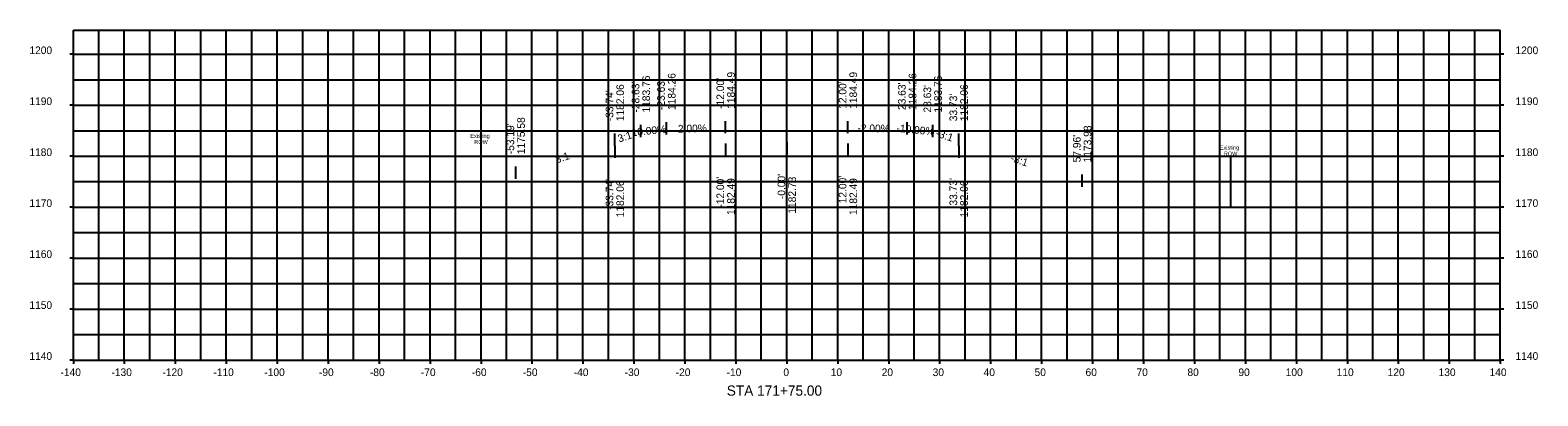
# Model space of a CAD drawing. Extents: x -148 to 147, y 1133 to 1205.
import ezdxf

# ---------------------------------------------------------------- set-up
doc = ezdxf.new("R2010")
doc.units = 0
for name, color, linetype in [('SheetBorder', 7, 'Continuous'), ('SheetGridMajor', 7, 'Continuous'), ('SheetGridMinor', 7, 'Continuous'), ('SheetText', 7, 'Continuous'), ('TC_Grading', 7, 'Continuous'), ('Text', 7, 'Continuous')]:
    doc.layers.add(name, color=color, linetype=linetype)

msp = doc.modelspace()

# ---------------------------------------------------------------- linework, layer by layer
at = {"layer": 'SheetBorder'}
for p, q in [((-140, 1204.73), (140, 1204.73)), ((-140, 1140), (-140, 1204.73)), ((140, 1140), (140, 1204.73)), ((-140, 1140), (140, 1140))]:
    msp.add_line(p, q, dxfattribs=at)
at = {"layer": 'SheetGridMajor'}
for p, q in [((-130, 1140), (-130, 1204.73)), ((-120, 1140), (-120, 1204.73)), ((-110, 1140), (-110, 1204.73)), ((-100, 1140), (-100, 1204.73)), ((-90, 1140), (-90, 1204.73)), ((-80, 1140), (-80, 1204.73)), ((-70, 1140), (-70, 1204.73)), ((-60, 1140), (-60, 1204.73)), ((-50, 1140), (-50, 1204.73)), ((-40, 1140), (-40, 1204.73)), ((-30, 1140), (-30, 1204.73)), ((-20, 1140), (-20, 1204.73)), ((-10, 1140), (-10, 1204.73)), ((0, 1140), (0, 1204.73)), ((10, 1140), (10, 1204.73)), ((20, 1140), (20, 1204.73)), ((30, 1140), (30, 1204.73)), ((40, 1140), (40, 1204.73)), ((50, 1140), (50, 1204.73)), ((60, 1140), (60, 1204.73)), ((70, 1140), (70, 1204.73)), ((80, 1140), (80, 1204.73)), ((90, 1140), (90, 1204.73)), ((100, 1140), (100, 1204.73)), ((110, 1140), (110, 1204.73)), ((120, 1140), (120, 1204.73)), ((130, 1140), (130, 1204.73)), ((-140, 1200), (-140.72, 1200)), ((-140, 1200), (140, 1200)), ((140.72, 1200), (140, 1200)), ((-140, 1190), (-140.72, 1190)), ((-140, 1190), (140, 1190)), ((140.72, 1190), (140, 1190)), ((-140, 1180), (-140.72, 1180)), ((-140, 1180), (140, 1180)), ((140.72, 1180), (140, 1180)), ((-140, 1170), (-140.72, 1170)), ((-140, 1170), (140, 1170)), ((140.72, 1170), (140, 1170)), ((-140, 1160), (-140.72, 1160)), ((-140, 1160), (140, 1160)), ((140.72, 1160), (140, 1160)), ((-140, 1150), (-140.72, 1150)), ((-140, 1150), (140, 1150)), ((140.72, 1150), (140, 1150)), ((-140, 1140), (-140.72, 1140)), ((-140, 1140), (-140, 1139.28)), ((-130, 1140), (-130, 1139.28)), ((-120, 1140), (-120, 1139.28)), ((-110, 1140), (-110, 1139.28)), ((-100, 1140), (-100, 1139.28)), ((-90, 1140), (-90, 1139.28)), ((-80, 1140), (-80, 1139.28)), ((-70, 1140), (-70, 1139.28)), ((-60, 1140), (-60, 1139.28)), ((-50, 1140), (-50, 1139.28)), ((-40, 1140), (-40, 1139.28)), ((-30, 1140), (-30, 1139.28)), ((-20, 1140), (-20, 1139.28)), ((-10, 1140), (-10, 1139.28)), ((0, 1140), (0, 1139.28)), ((10, 1140), (10, 1139.28)), ((20, 1140), (20, 1139.28)), ((30, 1140), (30, 1139.28)), ((40, 1140), (40, 1139.28)), ((50, 1140), (50, 1139.28)), ((60, 1140), (60, 1139.28)), ((70, 1140), (70, 1139.28)), ((80, 1140), (80, 1139.28)), ((90, 1140), (90, 1139.28)), ((100, 1140), (100, 1139.28)), ((110, 1140), (110, 1139.28)), ((120, 1140), (120, 1139.28)), ((130, 1140), (130, 1139.28)), ((140, 1140), (140, 1139.28)), ((140.72, 1140), (140, 1140))]:
    msp.add_line(p, q, dxfattribs=at)
at = {"layer": 'SheetGridMinor'}
for p, q in [((-135, 1140), (-135, 1204.73)), ((-125, 1140), (-125, 1204.73)), ((-115, 1140), (-115, 1204.73)), ((-105, 1140), (-105, 1204.73)), ((-95, 1140), (-95, 1204.73)), ((-85, 1140), (-85, 1204.73)), ((-75, 1140), (-75, 1204.73)), ((-65, 1140), (-65, 1204.73)), ((-55, 1140), (-55, 1204.73)), ((-45, 1140), (-45, 1204.73)), ((-35, 1140), (-35, 1204.73)), ((-25, 1140), (-25, 1204.73)), ((-15, 1140), (-15, 1204.73)), ((-5, 1140), (-5, 1204.73)), ((5, 1140), (5, 1204.73)), ((15, 1140), (15, 1204.73)), ((25, 1140), (25, 1204.73)), ((35, 1140), (35, 1204.73)), ((45, 1140), (45, 1204.73)), ((55, 1140), (55, 1204.73)), ((65, 1140), (65, 1204.73)), ((75, 1140), (75, 1204.73)), ((85, 1140), (85, 1204.73)), ((95, 1140), (95, 1204.73)), ((105, 1140), (105, 1204.73)), ((115, 1140), (115, 1204.73)), ((125, 1140), (125, 1204.73)), ((135, 1140), (135, 1204.73)), ((-140, 1195), (140, 1195)), ((-140, 1185), (140, 1185)), ((-140, 1175), (140, 1175)), ((-140, 1165), (140, 1165)), ((-140, 1155), (140, 1155)), ((-140, 1145), (140, 1145))]:
    msp.add_line(p, q, dxfattribs=at)
at = {"layer": 'TC_Grading'}
for p, q in [((-60.01, 1182.24), (-60.01, 1172.39)), ((87.07, 1179.94), (87.07, 1170.1))]:
    msp.add_line(p, q, dxfattribs=at)
at = {"layer": 'Text'}
for p, q in [((-23.63, 1184.26), (-23.63, 1186.66)), ((-12, 1184.49), (-12, 1186.89)), ((12, 1184.49), (12, 1186.89)), ((23.63, 1184.26), (23.63, 1186.66)), ((-33.74, 1182.06), (-33.74, 1184.46)), ((-28.63, 1183.76), (-28.63, 1186.16)), ((28.63, 1183.76), (28.63, 1186.16)), ((33.73, 1182.06), (33.73, 1184.46)), ((33.73, 1182.06), (33.73, 1184.46)), ((-33.74, 1182.06), (-33.74, 1179.66)), ((-12, 1182.49), (-12, 1180.09)), ((0, 1182.73), (0, 1180.33)), ((12, 1182.49), (12, 1180.09)), ((33.73, 1182.06), (33.73, 1179.66)), ((-53.19, 1175.58), (-53.19, 1177.98)), ((57.96, 1173.98), (57.96, 1176.38))]:
    msp.add_line(p, q, dxfattribs=at)

# ---------------------------------------------------------------- texts
at = {"layer": 'SheetText'}
for s, height, p in [('1200', 1.5, (-148.63, 1200.03)), ('1200', 1.5, (143, 1200.03)), ('1190', 1.5, (-148.63, 1190.03)), ('1190', 1.5, (143, 1190.03)), ('1180', 1.5, (-148.63, 1180.03)), ('1180', 1.5, (143, 1180.03)), ('1170', 1.5, (-148.63, 1170.03)), ('1170', 1.5, (143, 1170.03)), ('1160', 1.5, (-148.63, 1160.03)), ('1160', 1.5, (143, 1160.03)), ('1150', 1.5, (-148.63, 1150.03)), ('1150', 1.5, (143, 1150.03)), ('1140', 1.5, (-148.63, 1140.03)), ('1140', 1.5, (143, 1140.03)), ('-140', 1.5, (-142.53, 1136.85)), ('-130', 1.5, (-132.53, 1136.85)), ('-120', 1.5, (-122.53, 1136.85)), ('-110', 1.5, (-112.53, 1136.85)), ('-100', 1.5, (-102.53, 1136.85)), ('-90', 1.5, (-91.81, 1136.85)), ('-80', 1.5, (-81.81, 1136.85)), ('-70', 1.5, (-71.81, 1136.85)), ('-60', 1.5, (-61.81, 1136.85)), ('-50', 1.5, (-51.81, 1136.85)), ('-40', 1.5, (-41.81, 1136.85)), ('-30', 1.5, (-31.81, 1136.85)), ('-20', 1.5, (-21.81, 1136.85)), ('-10', 1.5, (-11.81, 1136.85)), ('0', 1.5, (-0.67, 1136.85)), ('10', 1.5, (8.62, 1136.85)), ('20', 1.5, (18.62, 1136.85)), ('30', 1.5, (28.62, 1136.85)), ('40', 1.5, (38.62, 1136.85)), ('50', 1.5, (48.62, 1136.85)), ('60', 1.5, (58.62, 1136.85)), ('70', 1.5, (68.62, 1136.85)), ('80', 1.5, (78.62, 1136.85)), ('90', 1.5, (88.62, 1136.85)), ('100', 1.5, (97.9, 1136.85)), ('110', 1.5, (107.9, 1136.85)), ('120', 1.5, (117.9, 1136.85)), ('130', 1.5, (127.9, 1136.85)), ('140', 1.5, (137.9, 1136.85)), ('STA 171+75.00', 2.004, (-11.78, 1133))]:
    msp.add_text(s, height=height, dxfattribs=at).set_placement(p)
at = {"layer": 'TC_Grading'}
for s, p in [('Existing', (-62.1, 1183.59)), ('ROW', (-61.33, 1182.41)), ('Existing', (84.98, 1181.29)), ('ROW', (85.76, 1180.11))]:
    msp.add_text(s, height=0.787, dxfattribs=at).set_placement(p)
at = {"layer": 'Text'}
for s, rotation, p in [('1183.76', 90, (-26.83, 1188.56)), ('1184.26', 90, (-21.83, 1189.06)), ('1184.49', 90, (-10.2, 1189.29)), ('1184.49', 90, (13.8, 1189.29)), ('1184.26', 90, (25.43, 1189.06)), ('1183.76', 90, (30.43, 1188.56)), ("-33.74'", 90, (-34.04, 1186.86)), ('1182.06', 90, (-31.94, 1186.86)), ("-28.63'", 90, (-28.93, 1188.56)), ("-23.63'", 90, (-23.93, 1189.06)), ("-12.00'", 90, (-12.3, 1189.29)), ("12.00'", 90, (11.7, 1189.29)), ("23.63'", 90, (23.33, 1189.06)), ("28.63'", 90, (28.33, 1188.56)), ('1182.06', 90, (35.53, 1186.86)), ('1182.06', 90, (35.53, 1186.86)), ("33.73'", 90, (33.43, 1186.86)), ("33.73'", 90, (33.43, 1186.86)), ('1175.58', 90, (-51.39, 1180.38)), ("-53.19'", 90, (-53.49, 1180.38)), ('3:1', 18.4332, (-32.88, 1182.67)), ('10.00%', 5.7106, (-30.37, 1183.91)), ('2.00%', 1.1458, (-21.35, 1184.63)), ('-2.00%', 358.8542, (13.85, 1184.78)), ('-10.00%', 354.2894, (21.47, 1184.8)), ('-3:1', 341.5668, (29.1, 1183.93)), ("57.96'", 90, (57.66, 1178.78)), ('1173.98', 90, (59.76, 1178.78)), ('3:1', 18.4332, (-45.15, 1178.58)), ('-3:1', 341.5668, (43.77, 1179.04)), ("-33.74'", 90, (-34.04, 1169.46)), ('1182.06', 90, (-31.94, 1167.99)), ("-12.00'", 90, (-12.3, 1169.89)), ('1182.49', 90, (-10.2, 1168.45)), ("-0.00'", 90, (-0.3, 1171.57)), ('1182.73', 90, (1.8, 1168.72)), ("12.00'", 90, (11.7, 1170.75)), ('1182.49', 90, (13.8, 1168.45)), ("33.73'", 90, (33.43, 1170.31)), ('1182.06', 90, (35.53, 1167.99))]:
    msp.add_text(s, height=1.5, rotation=rotation, dxfattribs=at).set_placement(p)

doc.saveas('drawing.dxf')
